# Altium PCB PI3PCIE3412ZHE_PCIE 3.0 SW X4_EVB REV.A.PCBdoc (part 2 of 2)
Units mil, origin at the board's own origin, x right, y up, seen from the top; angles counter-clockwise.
Board outline 3399 x 2712 mil, 8 copper layers (TopLayer, InternalPlane1, MidLayer1, MidLayer2, MidLayer3, MidLayer4, InternalPlane2, BottomLayer); 24 components, 100 nets, 589 pads, 111 vias.
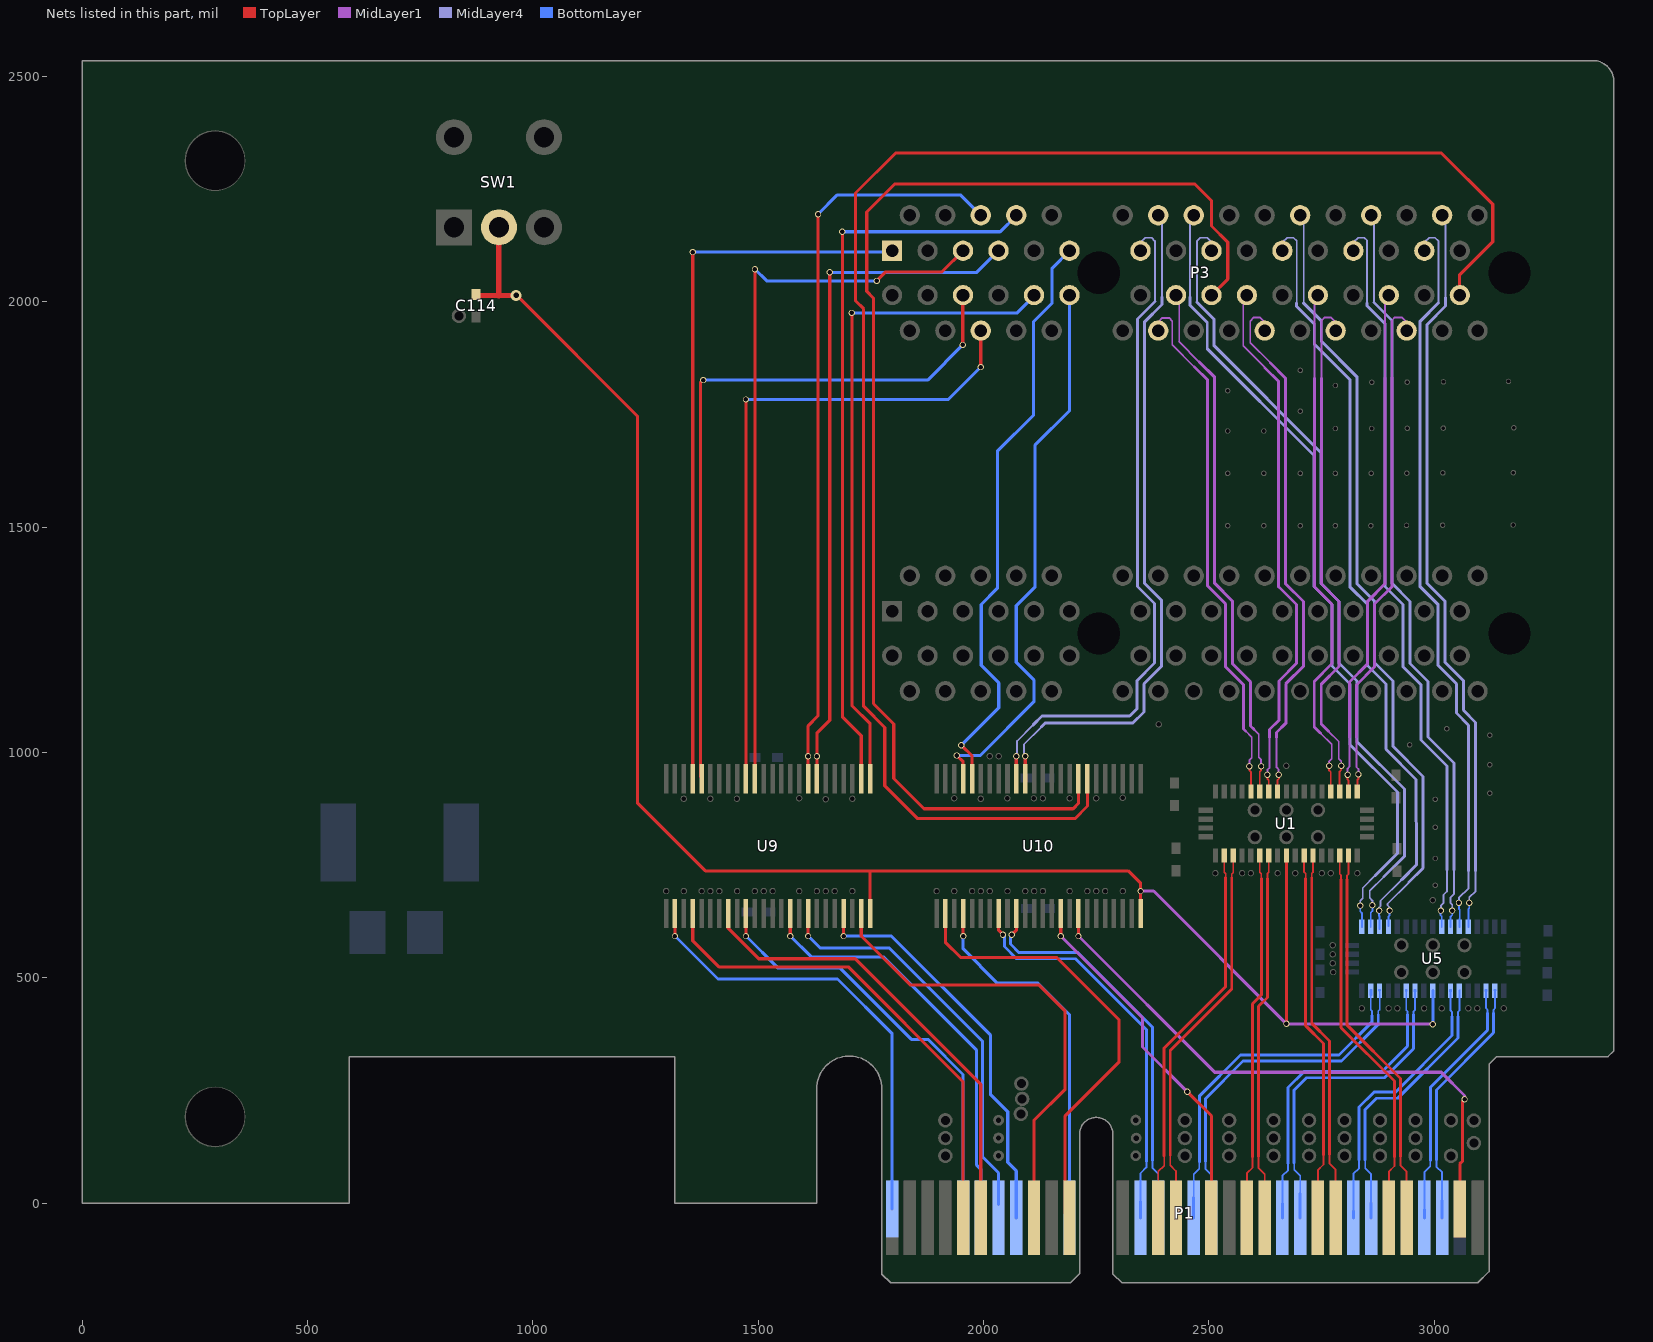
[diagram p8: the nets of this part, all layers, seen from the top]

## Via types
v1: diameter 14, hole 10, TopLayer to BottomLayer, tented both sides, 49 vias
v2: diameter 32, hole 20, TopLayer to BottomLayer, tented both sides, 40 vias
v3: diameter 24, hole 12, TopLayer to BottomLayer, tented both sides, 17 vias
v4: diameter 20, hole 10, TopLayer to BottomLayer, 5 vias

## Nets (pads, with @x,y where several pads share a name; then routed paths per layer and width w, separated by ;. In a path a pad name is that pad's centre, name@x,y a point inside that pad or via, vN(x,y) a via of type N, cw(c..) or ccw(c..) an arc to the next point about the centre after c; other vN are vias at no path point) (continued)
S1_JTAG1: P3.B9 U9.25 | length 1473.6
  TopLayer w7: v1(1708,1975) 1708,1934.76 1708,1104 1748.62,1063.38 U9.25@1748.62,941.61
  BottomLayer w7: v1(1708,1975) 2075.38,1975.38 P3.B9@2115,2015
S1_JTAG2: P3.A5 U9.38 | length 1632.3
  TopLayer w7: U9.38@1492.72,941.61 v1@1492.72,2072 ; v1(1763,2046) 1783,2066 1908,2066 P3.A5@1956,2114
  BottomLayer w7: v1(1493,2072) 1519,2046 v1(1763,2046)
S1_JTAG3: P3.A6 U9.32 | length 1660.2
  TopLayer w7: U9.32@1610.83,941.61 1610.83,1058.83 1633,1081 v1@1633,2195
  BottomLayer w7: v1(1633,2194) 1676,2237 1948.83,2237 P3.A6@1994.09,2191.73
  other v1: 1610.83,991.53
S1_JTAG4: P3.A7 U9.31 | length 1530.5
  TopLayer w7: U9.31@1630.51,941.61 1630.51,1042.51 1659,1071 v1(1659,2065)
  BottomLayer w7: v1(1659,2065) 1985,2065 P3.A7@2034,2114
  other v1: 1630.51,991.53
S1_JTAG5: P3.A8 U9.26 | length 1631.6
  TopLayer w7: v1(1687,2155) 1687,1079 1728.94,1037.06 U9.26@1728.94,943.06
  BottomLayer w7: v1@1686,2155 2037,2155 P3.A8@2073.28,2191.28
S1_PERN0: P3.A17 pad.2 U5.23 | length 1806.5
  MidLayer4 w4: 2473.5,1999 2473.5,2134.5 2481,2142 2497,2142 2505.91,2133.09 P3.A17@2505.91,2112.99 ; pad.2@2863,661 2863,671 2857,677 2857,692.5 2889,724.5
  MidLayer4 w6.5: 2473.5,1999 2512,1960.5 2512,1902 2749,1665 2749,1375 2789,1335 2789,1198.5 2829,1158.5 2829,1023.5 2934,918.5 2934,769.5 2889,724.5
  BottomLayer w4: U5.23@2859.45,611.88 2859.45,644.45 2863,648 pad.2@2863,659
S1_PERN1: P3.A22 pad.4 U5.25 | length 1727
  MidLayer4 w4: P3.A22@2702,2191 2710.5,2186 2710.5,1996.5 ; pad.4@2901,649 2901,656 2896.5,660.5 2896.5,664 2944.5,712
  MidLayer4 w6.5: 2710.5,1996.5 2749.5,1957.5 2749.5,1912.5 2828.5,1833.5 2828.5,1374.5 2867.5,1335.5 2867.5,1199.5 2908.5,1158.5 2908.5,1013.5 2975.5,946.5 2975.5,743 2944.5,712
  BottomLayer w4: U5.25@2899,614 2899,636 2901,638 pad.4@2901,649
S1_PERN2: P3.A26 pad.6 U5.32 | length 1661.9
  MidLayer4 w4: P3.A26@2860,2191 2866.5,2185 2866.5,1998 ; pad.6@3040,649 3040,662 3036,666 3036,677 3044,685 3044,739
  MidLayer4 w6.5: 2866.5,1998 2906.5,1958 2906.5,1375 2946.5,1335 2946.5,1197 2986.5,1157 2986.5,1034 3044,976.5 3044,739
  BottomLayer w4: U5.32@3036.61,611.88 3036.61,635.61 3040,639 pad.6@3040,649
S1_PERN3: P3.A30 pad.8 U5.34 | length 1650.9
  MidLayer4 w4: P3.A30@3017.42,2191.34 3025.5,2183.26 3025.5,2009.5 ; pad.8@3078,666 3078,678 3092,692 3092,736.5
  MidLayer4 w6.5: 3025.5,2009.5 3025.5,1990.5 2984.5,1949.5 2984.5,1374.5 3024.5,1334.5 3024.5,1199.5 3065,1159 3065,1093.5 3092,1066.5 3092,736.5
  BottomLayer w4: U5.34@3075.98,611.88 3076,652 3078,654 pad.8@3078,666
S1_PERP0: P3.A16 pad.1 U5.22 | length 1809.3
  MidLayer4 w4: 2458,2010 2458,2183.1 P3.A16@2466.24,2191.34 ; pad.1@2836,660 2836,671 2841.5,676.5 2841.5,699 2869.5,727
  MidLayer4 w6.5: 2458,2010 2458,1992 2496.5,1953.5 2496.5,1895.5 2733.5,1658.5 2733.5,1368 2773.5,1328 2773.5,1191.5 2813.5,1151.5 2813.5,1017 2918.5,912 2918.5,776 2869.5,727
  BottomLayer w4: pad.1@2836,660 2836,647 2839.76,643.24 U5.22@2839.76,611.88
S1_PERP1: P3.A21 pad.3 U5.24 | length 1728.7
  MidLayer4 w4: P3.A21@2663.39,2112.99 2663.39,2131.39 2674,2142 2688,2142 2695,2135 2695,1997 ; pad.3@2878,649 2878,656 2881,659 2881,670.5 2928,717.5
  MidLayer4 w6.5: 2695,1997 2695,1989.5 2734,1950.5 2734,1906 2813,1827 2813,1367.5 2852,1328.5 2852,1192.5 2893,1151.5 2893,1007 2960,940 2960.5,750 2928,717.5
  BottomLayer w4: pad.3@2878,649 2878,637 2879,636 U5.24@2879,608
S1_PERP2: P3.A25 pad.5 U5.31 | length 1660.3
  MidLayer4 w4: P3.A25@2820.87,2112.99 2820.87,2131.39 2831.48,2142 2845.48,2142 ; 2845,2142 2851,2136 2851,1997 ; pad.5@3015,649 3015,660 3020.5,665.5 3020.5,683.5 3028.5,691.5 3028.5,739
  MidLayer4 w6.5: 2851,1997 2851,1991 2891,1951 2891,1368 2931,1328 2931,1190 2971,1150 2971,1027.5 3028.5,970 3028.5,739
  BottomLayer w4: pad.5@3014,649 3014,639 3016.93,636.07 U5.31@3016.93,611.88
S1_PERP3: P3.A29 pad.7 U5.33 | length 1652.1
  MidLayer4 w4: 2978.35,2131.39 2988.96,2142 ; 2988,2142 3002,2142 3010,2134 3010,1997.5 ; pad.7@3055,666 3055,677 3076.5,698.5 3076.5,736.5
  MidLayer4 w6.5: P3.A29@2978.35,2112.99 2978.35,2131.39 ; 3010,1997.5 2969,1956.5 2969,1367.5 3009,1327.5 3009,1192.5 3049.5,1152 3049.5,1087 3076.5,1060 3076.5,736.5
  BottomLayer w4: pad.7@3055,666 3054.88,653.1 3056.86,651.08 U5.33@3056.5,611.88
S1_PERST#: P3.A11 U10.44 | length 1312.9
  TopLayer w7: v1(1951,1016) 1974.61,992.39 U10.44@1974.61,941.61
  BottomLayer w7: v1(1951,1016) 2034,1099 2034,1154.24 1995,1193.24 1995,1328 2031,1364 2031,1668 2111,1748 2111,1955.76 2152.24,1997 2152.24,2074.3 P3.A11@2190.95,2112.99
S1_PETN0: P3.B15 pad.14 U1.33 | length 1182.6
  TopLayer w4: U1.33@2613.19,911.88 2613.04,957.03 2616.03,960.03 pad.14@2616,969
  MidLayer1 w4: P3.B15@2427.17,2014.57 P3.B15@2434.74,2007 ; 2434,1911 2479,1866 ; 2434.5,1911 P3.B15@2434.5,2007 ; 2600,1051 2611,1040 2611,989 2616,984 pad.14@2616,969
  MidLayer1 w6.5: 2479,1866 2513,1832.5 2513,1375 2552.5,1335.5 2552.5,1196.5 2592.5,1156.5 2592.5,1058.5 2600,1051
S1_PETN1: P3.B20 pad.16 U1.31 | length 1183.7
  TopLayer w4: U1.31@2652.56,908.14 2652.56,938.56 2656,942 pad.16@2656,950
  MidLayer1 w4: P3.B20@2624.02,1935.83 2624.02,1953.98 2613,1965 2600,1965 2592,1957 2592,1908.5 2637,1864 ; 2650.5,1033 2650.5,966.5 2655,962 pad.16@2655,950
  MidLayer1 w6.5: 2637,1864 2670.5,1830 2670.5,1374 2710,1334.5 2710,1191 2671,1152 2671,1064.5 2650.5,1044 2650.5,1033
S1_PETN2: P3.B24 pad.18 U1.24 | length 1153.6
  TopLayer w4: U1.24@2790.35,911.88 2790.35,957.35 2794,961 pad.18@2794,970
  MidLayer1 w4: 2750,1831 2750,1958 2757,1965 2770.48,1965 2781.5,1953.98 P3.B24@2781.5,1935.83 ; 2765.5,1047 2788.5,1024 ; 2788.41,1021.83 2788.41,985.59 2794,980 pad.18@2794,970
  MidLayer1 w6.5: 2750,1831 2750,1373.5 2789,1334.5 2789,1190.5 2749.5,1151 2749.5,1063 2765.5,1047
S1_PETN3: P3.B28 pad.20 U1.22 | length 1143.8
  TopLayer w4: U1.22@2829.72,908.14 2829.72,938.72 2832,941 pad.20@2832,951
  MidLayer1 w4: 2827.5,1033.5 2827.5,967.5 2832,963 pad.20@2832,951 ; 2906.5,1831.5 2906.5,1958.54 2912.96,1965 2927.96,1965 2938.98,1953.98 P3.B28@2938.98,1935.83
  MidLayer1 w6.5: 2827.5,1033.5 2827.5,1149.5 2868,1190 2868,1329 2906.5,1367.5 2906.5,1831.5
S1_PETP0: P3.B14 pad.13 U1.34 | length 1178.7
  TopLayer w4: pad.13@2590,969 2590,960 2593.5,956.5 U1.34@2593.5,911.88
  MidLayer1 w4: P3.B14@2387.8,1935.83 2387.8,1954.8 2397,1964 2412,1964 2419,1957 2419,1904.5 2468,1855 ; 2581.5,1047.5 2595.5,1033.5 2595.5,988 2590,982.5 pad.13@2590,969
  MidLayer1 w6.5: 2468,1855 2497.5,1826 2497.5,1369 2537,1329.5 2537,1190 ; 2537.24,1190 2577,1150 2577,1052 2581.5,1047.5
S1_PETP1: P3.B19 pad.15 U1.32 | length 1185.9
  TopLayer w4: pad.15@2630,950 2630,941 2632.87,938.13 U1.32@2632.87,908.14
  MidLayer1 w4: P3.B19@2584.35,2014.17 2576.5,2006.33 2576.5,1902 2625,1853 ; pad.15@2630,950 2630,961 2635,966 2635,1032.5
  MidLayer1 w6.5: 2625,1853 2655,1823.5 2655,1367 ; 2635,1032.5 2635,1050.5 2655.5,1071 2655.5,1158.5 2694.5,1197.5 2694.5,1328 2655.5,1367
S1_PETP2: P3.B23 pad.17 U1.25 | length 1157.3
  TopLayer w4: pad.17@2767,970 2767,960 2770.67,956.33 U1.25@2770.67,911.88
  MidLayer1 w4: 2734.5,1830 2734.5,2006.35 P3.B23@2741.83,2013.67 ; 2747.5,1043 2773,1017.5 ; pad.17@2767,970 2767,980 2772.91,985.91 2772.91,1017.33
  MidLayer1 w6.5: 2734.5,1830 2734.5,1367.5 2773.5,1328.5 2773.5,1197 2734,1157.5 2734,1056.5 2747.5,1043
S1_PETP3: P3.B27 pad.19 U1.23 | length 1144.7
  TopLayer w4: pad.19@2808,950 2808,940 2810.04,937.96 U1.23@2810.04,908.14
  MidLayer1 w4: pad.19@2808,950 2808,964 2812,968 2812,1033.5 ; 2891,1831 2891,2005.87 P3.B27@2899.31,2014.17
  MidLayer1 w6.5: 2812,1033.5 2812,1156 2852.5,1196.5 2852.5,1335.5 2891,1374 2891,1831
S1_PRSNT1#: P3.A1 U9.45 | length 1606.4
  TopLayer w7: U9.45@1354.92,941.61 v1@1354.92,2110
  BottomLayer w7: v1(1355,2110) P3.A1@1793,2110
S1_PRSNT2#: P3.B17 U10.32 | length 2826.3
  TopLayer w7: U10.32@2210.83,941.61 2210.94,887.06 2198.88,875 1868,875 1801,942 1801,1063 1756,1108 1756,2008 1741,2023 1741,2199 1803,2261 2469,2261 2506,2224 2506,2168 2542,2132 2542,2050 P3.B17@2505,2013
S1_PRSNT3#: P3.B31 U10.31 | length 3627.1
  TopLayer w7: U10.31@2230.51,941.61 2230.89,903.12 2230.89,880.89 2203,853 1854,853 1781,926 1781,1055 1734,1102 1734,1984 1716,2002 1716,2241 1805,2330 3016,2330 3130,2216 3130,2133 3056,2059 P3.B31@3056,2012
S1_REFCLK+: P3.A13 pad.11 U10.39 | length 1524.1
  TopLayer w7.5: U10.39@2073.03,941.61 pad.11@2073.03,991.53
  MidLayer4 w4: pad.11@2073,991 2074.5,993 2074.5,1025 2110.5,1061 ; P3.A13@2348.43,2112.99 2348.42,2131.39 2359.04,2142 2373.04,2142 ; 2373,2142 2380.5,2134.5 2380.5,2000.5
  MidLayer4 w6.5: 2110.5,1061 2130,1080.5 2324.5,1080.5 2340.5,1096.5 2340.5,1159 2379.5,1198 2379.5,1330 2341.5,1368 2341.5,1961.5 2380.5,2000.5
S1_REFCLK-: P3.A14 pad.12 U10.38 | length 1526.8
  TopLayer w7.5: U10.38@2092.72,941.61 pad.12@2092.72,991.53
  MidLayer4 w4: pad.12@2092,991 2090,993 2090,1018 2129,1057 ; P3.A14@2387.49,2191.34 2396,2182.83 2396,2010
  MidLayer4 w6.5: 2129,1057 2137,1065 2331.5,1065 2356,1089.5 2356,1152 2395,1191 2395,1337.5 2357,1375.5 2357,1954.5 2396,1993.5 2396,2010
S1_SMCLK: P3.B5 U9.44 | length 1604.2
  TopLayer w7: U9.44@1372,946 1372,1820 v1(1378,1826) ; U9.44@1374.61,941.61 U9.44@1374.61,946 ; v1(1954,1904) P3.B5@1954,2013
  BottomLayer w7: v1(1378,1826) 1876,1826 v1(1954,1904)
S1_SMDAT: P3.B6 U9.39 | length 1473.2
  TopLayer w7: U9.39@1473.03,941.61 v1(1473,1783) ; v1(1994,1855) P3.B6@1994,1936
  BottomLayer w7: v1(1473,1783) 1922,1783 v1(1994,1855)
S1_WAKE#: P3.B11 U10.45 | length 1246.3
  TopLayer w7: v1(1941,993) 1954.92,979.08 U10.45@1954.92,941.61
  BottomLayer w7: v1(1941,993) 1993,993 2112,1112 2112,1160.83 2072.83,1200 2072.83,1326.16 ; 2072.83,1325 2114,1366.16 2114,1681 2190.94,1757.94 P3.B11@2190.95,2014.57
S_JTAG1: P1.B9 U9.23 | length 1058.5
  TopLayer w7: U9.23@1728.94,642.39 1728.94,592.47 1837.41,484 2123,484 2181.1,425.9 2181.1,252.43 2112.2,183.54 P1.B9@2112.2,-33
S_JTAG2: P1.A5 U9.10 | length 977.1
  TopLayer w7: v1(1473.03,592.47) U9.10@1473.03,642.39
  BottomLayer w7: v1(1473.03,592.47) 1543.5,522 1681,522 1840,363 1877,363 1954.72,285.28 P1.A5@1954.72,-33
S_JTAG3: P1.A6 U9.15 | length 885.2
  TopLayer w7: v1(1571.46,592.47) U9.15@1571.46,642.39
  BottomLayer w7: v1(1571.46,592.47) 1617.76,546.17 1777.83,546.17 1984.26,339.74 1984.26,85.12 1994.09,75.28 P1.A6@1994.09,26.06
S_JTAG4: P1.A7 U9.17 | length 911
  TopLayer w7: v1(1610.83,592.47) U9.17@1610.83,642.39
  BottomLayer w7: v1(1610.83,592.47) 1637.45,565.85 1791.15,565.85 1998,359 1998,102.24 2033.46,66.78 P1.A7@2033.46,-3.47
S_JTAG5: P1.A8 U9.21 | length 896.2
  TopLayer w7: v1(1689.57,592.47) U9.21@1689.57,642.39
  BottomLayer w7: v1(1689.57,592.47) 1795.53,592.47 2016,372 2016,240.39 2054,202.39 2054,90.24 2072.83,71.41 P1.A8@2072.83,-33
S_PERN0: P1.A17 U5.15 | length 799.8
  BottomLayer w4: 2492.5,92 2492.5,76.5 2505.91,63.09 P1.A17@2505.91,18 ; 2876,417 2876,426 2879.13,429.13 U5.15@2879.13,472.12
  BottomLayer w6.5: 2492.5,92 2492.5,231.5 2576,315 2794.5,315 2876,396.5 2876,417 ; P1.A17@2505.91,-33 P1.A17@2505.91,18 ; U5.15@2879.13,471.13 U5.15@2879.13,472.12
S_PERN1: P1.A22 U5.11 | length 723.4
  BottomLayer w4: 2689.5,89 2689.5,73.5 2702.76,60.24 P1.A22@2702.76,21 ; 2954.5,418 2954.5,425.5 2957.89,428.89 U5.11@2957.89,469.7
  BottomLayer w6.5: 2689.5,89 2689.5,251 2716.5,278 2890,278 2954.5,342.5 2954.5,418 ; P1.A22@2702.76,-33 P1.A22@2702.76,21 ; U5.11@2957.89,469.7 2957.88,471.14 U5.11@2957.87,472.12
S_PERN2: P1.A26 U5.6 | length 625.3
  BottomLayer w4: 2847,96 2847,77 2860.24,63.76 P1.A26@2860.24,0 ; 3053,414 3053,424.5 3056.5,428 3056.5,471.92 U5.6@3056.3,472.12
  BottomLayer w6.5: 2847,96 2847,207.5 2872,232.5 2919.5,232.5 3053,366 3053,414 ; P1.A26@2860.24,-33 P1.A26@2860.24,0
S_PERN3: P1.A30 U5.2 | length 564.2
  BottomLayer w4: 3005,95 3005,80.72 3017.72,68 P1.A30@3017.72,5 ; 3132,422 3132,429 3135,432 3135,471.1 U5.2@3135.04,471.13
  BottomLayer w6.5: 3005,95 3005,251 3132,378 3132,422 ; P1.A30@3017.72,-33 P1.A30@3017.72,5 ; U5.2@3135.04,471.13 U5.2@3135.04,472.12
S_PERP0: P1.A16 U5.16 | length 798.3
  BottomLayer w4: P1.A16@2466.53,12 2466.53,64 2479,76.47 2479,91 ; U5.16@2859.45,462 2859.45,428.55 2862.39,425.61 2862.39,416.11
  BottomLayer w6.5: P1.A16@2466.53,-33 P1.A16@2466.53,12 ; 2479,91 2479,237 2570.5,328.5 2789,328.5 2862.5,402 2862.5,416.11 ; U5.16@2859.45,462 U5.16@2859.45,472.12
S_PERP1: P1.A21 U5.12 | length 723.1
  BottomLayer w4: P1.A21@2663.39,-1 2663.39,60.39 2676,73 2676,88 ; U5.12@2938.18,471.13 2938,470.95 2938,428 2941,425 2941,418
  BottomLayer w6.5: P1.A21@2663.39,-33 P1.A21@2663.39,-1 ; 2676,88 2676,256.5 2711,291.5 2884.5,291.5 2941,348 2941,418 ; U5.12@2938.18,471.13 U5.12@2938.19,472.12
S_PERP2: P1.A25 U5.7 | length 624.7
  BottomLayer w4: P1.A25@2820.89,-17.44 2820.89,65 2833.5,77.61 2833.5,95 ; U5.7@3036.6,469.7 3036.6,427.4 3039.5,424.5 3039.5,414
  BottomLayer w6.5: P1.A25@2820.87,-33 P1.A25@2820.89,-17.44 ; 2833.5,95 2833.5,213 2866.5,246 2914,246 3039.5,371.5 3039.5,414 ; U5.7@3036.6,469.7 3036.61,471.13 U5.7@3036.61,472.12
S_PERP3: P1.A29 U5.3 | length 564.5
  BottomLayer w4: P1.A29@2978.35,-14 2978.35,68 2991.5,81.15 2991.5,94 ; U5.3@3115.37,470.18 3115.37,432.13 3118.5,429 3118.5,421
  BottomLayer w6.5: P1.A29@2978.35,-33 P1.A29@2978.35,-14 ; 2991.5,94 2991.5,256.5 3118.5,383.5 3118.5,421 ; U5.3@3115.37,470.18 3115.36,471.14 U5.3@3115.35,472.12
S_PERST#: P1.A11 U10.4 | length 825.9
  TopLayer w7: v1(1954.92,592.47) U10.4@1954.92,642.39
  BottomLayer w7: v1(1954.92,592.47) 1954.92,564.08 2031,488 2121,488 2190.94,418.06 P1.A11@2190.94,-33
S_PETN0: P1.B15 U1.3 | length 872.7
  TopLayer w4: 2414.5,106 2414.5,83.5 2426.96,71.04 P1.B15@2426.96,21.32 ; 2551,721 2551,730 2554.13,733.13 U1.3@2554.13,772
  TopLayer w6.5: 2414.5,106 2414.5,338.5 2551,475 2551,721 ; P1.B15@2427.06,21.32 P1.B15@2427.16,-33 ; U1.3@2554.13,771.13 U1.3@2554.13,775.86
S_PETN1: P1.B20 U1.7 | length 825.5
  TopLayer w4: 2610.59,102.9 2610.59,77.47 2624.02,64.05 P1.B20@2624.02,17 ; 2630,720 2630,731 2632.89,733.89 U1.7@2632.89,773.08
  TopLayer w6.5: 2610.5,103 2610.5,436.5 2630,456 2630,720 ; P1.B20@2624.02,-33 P1.B20@2624.02,17 ; U1.7@2632.89,771.13 2632.89,773.08 U1.7@2632.87,775.86
S_PETN2: P1.B24 U1.12 | length 832.8
  TopLayer w4: 2728.5,721 2728.5,731.5 2731.33,734.33 U1.12@2731.33,771.97 ; 2768,108 2768,86.97 2781.42,73.55 2781.42,2.07 P1.B24@2781.5,2
  TopLayer w6.5: 2728.5,721 2728.5,399 2768,359.5 2768,108 ; U1.12@2731.3,775.86 2731.33,771.97 U1.12@2731.3,771.13 ; P1.B24@2781.5,-33 P1.B24@2781.5,2
S_PETN3: P1.B28 U1.16 | length 864.8
  TopLayer w4: 2807,718 2807,727 2810,730 U1.16@2810,770.96 ; 2925.5,103 2925.5,82.48 2938.92,69.06 2938.92,29.06 2938.98,29 P1.B28@2938.98,11
  TopLayer w6.5: 2807,718 2807,394.5 2925.5,276 2925.5,103 ; U1.16@2810.04,770.96 U1.16@2810.04,775.86 ; P1.B28@2938.98,-33 P1.B28@2938.98,11
S_PETP0: P1.B14 U1.2 | length 872.1
  TopLayer w4: P1.B14@2387.91,13.58 2388.04,13.72 2388.04,70.04 2401,83 2401,104 ; U1.2@2534.45,771.13 2534.45,733.55 2537.5,730.5 2537.5,722
  TopLayer w6.5: P1.B14@2387.8,-33 P1.B14@2387.91,13.58 ; 2401,104 2401,344 2537.5,480.5 2537.5,722 ; U1.2@2534.45,771.13 U1.2@2534.45,775.86
S_PETP1: P1.B19 U1.6 | length 823.5
  TopLayer w4: P1.B19@2584.65,17 2584.65,65.69 2597,78.05 2597,102 ; U1.6@2613,772.44 2613,734 2616.5,730.5 2616.5,720
  TopLayer w6.5: P1.B19@2584.65,-33 P1.B19@2584.65,17 ; 2597,102 2597,442 2616.5,461.5 2616.5,720 ; U1.6@2613.17,772.43 U1.6@2613.19,775.86
S_PETP2: P1.B23 U1.11 | length 831.8
  TopLayer w4: U1.11@2711.5,773.77 2711.5,734.5 2715,731 2715,720 ; P1.B23@2742.13,14 2742.13,73.16 2754.5,85.54 2754.5,107
  TopLayer w6.5: U1.11@2711.61,773.77 U1.11@2711.61,775.86 ; 2715,720 2715,393.5 2754.5,354 2754.5,107 ; P1.B23@2742.13,-33 P1.B23@2742.13,14
S_PETP3: P1.B27 U1.15 | length 864.4
  TopLayer w4: U1.15@2790.38,770.22 2790.38,730.12 2793.5,727 2793.5,718 ; P1.B27@2899.61,-16 2899.61,69.68 2912,82.08 2912,102
  TopLayer w6.5: U1.15@2790.35,775.86 U1.15@2790.35,771.13 U1.15@2790.38,770.22 ; 2793.5,718 2793.5,389 2912,270.5 2912,102 ; P1.B27@2899.61,-33 P1.B27@2899.61,-16
S_PRSNT1#: P1.A1 U9.2 | length 1010.5
  TopLayer w7: v1(1315.55,592.47) U9.2@1315.55,642.39
  BottomLayer w7: v1(1315.55,592.47) 1411.07,496.95 1676.05,496.95 1797.24,375.76 P1.A1@1797.24,-13.32
S_PRSNT2#: P1.B17 U10.15 | length 813.9
  TopLayer w7: v1(2171.46,592.47) U10.15@2171.46,642.39 ; v1(2452.24,247) 2505.91,193.34 P1.B17@2505.91,-33
  MidLayer1 w7: v1(2171.46,592.47) 2353,410.93 2353,346.24 v1(2452.24,247)
S_PRSNT3#: P1.B31 U10.17 | length 1309.4
  TopLayer w7: v1(2210.83,592.47) U10.17@2210.83,642.39 ; P1.B31@3057.09,-13.32 3057.09,86.84 3063,92.61 3063,225.5 v1(3067.5,230)
  MidLayer1 w7: v1(2210.83,592.47) 2513.3,290 3016,290 3067.5,238.5 v1(3067.5,230)
S_REFCLK+: P1.A13 U10.8 | length 893
  TopLayer w7: U10.8@2033.66,642.39 2033.66,604.99 v1(2043.31,595.35)
  BottomLayer w4: P1.A13@2348.42,3 2348.42,66 2361.5,79.07 2361.5,92
  BottomLayer w6.5: v1(2043.31,595.35) 2046.5,592 2046.5,569 2073.5,542 2204,542 2361.5,384.5 2361.5,92 ; P1.A13@2348.42,-33 P1.A13@2348.42,3
S_REFCLK-: P1.A14 U10.10 | length 892.9
  TopLayer w7: v1(2062.99,595.35) 2073.03,605.39 U10.10@2073.03,642.39
  BottomLayer w4: 2375,94 2375,78 2387.8,65.2 P1.A14@2387.8,20
  BottomLayer w6.5: v1(2062.99,595.35) 2060,592 2060,574.5 2079,555.5 2209.5,555.5 2375,390 2375,94 ; P1.A14@2387.8,-33 P1.A14@2387.8,20
S_SMCLK: P1.B5 U9.4 | length 1092
  TopLayer w7: U9.4@1354.92,642.39 1354.92,582.08 1413,524 1700,524 1954.72,269.28 P1.B5@1954.72,-33
S_SMDAT: P1.B6 U9.8 | length 1033
  TopLayer w7: U9.8@1433.66,642.39 1433.66,609.34 1501,542 1715.24,542 1994.09,263.15 P1.B6@1994.09,-33
S_WAKE#: P1.B11 U10.2 | length 1013.6
  TopLayer w7: U10.2@1915.55,642.39 1915.55,578.45 1949,545 2162,545 2301,406 2301,313.28 2181.1,193.38 2181.1,-23.16 P1.B11@2190.94,-33
SEL_3.3: C114.1 SW1.2 U1.9 U5.9 U9.24 U10.24 | length 4050
  TopLayer w7: v3(963,2014) v3@964.24,2011 ; v3@964.24,2014 1232,1746.24 1232,888 1383,737 2321,737 2348.62,709.38 U10.24@2348.62,642.39 ; U9.24@1748.62,642.39 1748.62,737 ; v1(2672.24,397.76) U1.9@2672.24,771.13
  TopLayer w12: C114.1@874.24,2013.5 v3(963,2014) ; 924.24,2013.5 SW1.2@924.24,2165
  MidLayer1 w7: v1(2348.62,692.32) 2377.68,692.32 v1(2672.24,397.76) ; v1@2673,397 v1(2997.24,397)
  BottomLayer w7: v1(2997.24,397) U5.9@2997.24,471.13
pads on no net: P2.165 P2.166 P3.165 P3.166 SW1.4 SW1.5 U9.14 U10.14 U10.21 U10.23 U10.25 U10.26 U10.28 U10.29

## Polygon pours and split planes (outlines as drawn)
no net on TopLayer "bottom Layer-No Net" (hatched 45Degree grid 70 track 30, remove dead copper, pour order 1001): 1145,2510 1659,2510 1661,2512 1661,2360 1474,2173 1201,2173 1150,2173 1145,2168 1144,2169 1144,2511
no net on TopLayer "bottom Layer-No Net" (hatched 45Degree grid 70 track 30, remove dead copper, pour order 1000): 421,2512 736,2512 737,2511 737,1906 735,1904 956,1904 1118,1742 1118,909 1117,908 422,908 421,907 421,2512
+3.3V on TopLayer "bottom Layer-No Net" (solid, pour order 1000): 2049,324 2174,324 2174,278 2133,237 2080,184 2059,184 2059,254 2049,264 2049,324
+3.3V on MidLayer2 "bottom Layer-No Net" (solid, remove dead copper, pour order 1001): 25,2512 3358,2512 3377,2493 3377,348 2311,348 2124,161 2047,161 2047,245 1996,296 1943,349 25,349 25,2512
GND on MidLayer3 "bottom Layer-No Net" (solid, remove dead copper, pour order 1001): 25,349 25,2512 3358,2512 3377,2493 3377,348 3376,349 25,349
+12V on MidLayer3 "bottom Layer-No Net" (solid, remove dead copper, pour order 1000): 1246,2513 1948,2513 1948,2157 1916,2125 1919,2122 1919,1980 1958,1941 1958,1928.02 1958,1389 1916,1347 1916,1181 1946,1151 1946,832 1983,795 1983,85 1791,85 1791,343 1463,671 1246,888 1246,2513
no net on BottomLayer "bottom Layer-No Net" (hatched 45Degree grid 70 track 30, remove dead copper, pour order 1003): 1142,2512 1657,2512 1659,2514 1659,2300 1555,2196 1552,2199 1142,2199 1142,2512
+3.3V on BottomLayer "bottom Layer-No Net" (solid, pour order 1002): 2094.14,283 2159.14,283 2181.14,261 2181.14,159 2068.14,159 2068.14,283 2094.14,283
no net on BottomLayer "bottom Layer-No Net" (hatched 90Degree grid 70 track 30, remove dead copper, pour order 1000): 423,2513 424,2512 737,2512 737,1904 952,1904 1117,1739 1118,1738 1118,1027 421,1027 420,1026 423,1029 423,2513
GND on InternalPlane1 (split plane): 3358.92,2513.83 3365.37,2511.16 3370.91,2506.91 3375.16,2501.37 3377.83,2494.92 3378.74,2488 3378.66,2487.43 3378.69,2487.43 3378.61,2487 3378.61,346.45 3377.55,345.39 3139,345.39 3131.2,343.84 3124.58,339.42 3107.58,322.41 3103.15,315.8 3101.6,307.99 3101.6,90.2 2307.64,90.2 2307.64,153 2307.74,153 2305.78,167.88 2300.03,181.75 2290.9,193.65 2278.99,202.79 2265.12,208.53 2250.24,210.49 2235.36,208.53 2221.5,202.79 2209.59,193.65 2200.45,181.75 2194.71,167.88 2192.75,153 2192.85,153 2192.85,80.2 1794.64,80.2 1794.64,254 1794.69,254 1792.91,272.04 1787.65,289.38 1779.11,305.36 1767.61,319.37 1753.6,330.87 1737.62,339.41 1720.28,344.67 1702.24,346.45 1684.21,344.67 1666.87,339.41 1650.88,330.87 1636.88,319.37 1625.38,305.36 1616.84,289.38 1611.58,272.04 1609.8,254 1609.85,254 1609.85,20.39 1335.64,20.39 1335.64,325 1334.08,332.8 1329.66,339.42 1323.05,343.84 1315.24,345.39 611.96,345.39 604.24,350.55 594.49,352.49 584.73,350.55 576.46,345.02 570.94,336.75 569,327 569,27.49 27.73,27.49 27.73,2414.17 29.49,2423 27.55,2432.75 22.02,2441.02 20.39,2442.11 20.39,2514.61 3353,2514.61
GND on InternalPlane2 (split plane): 3358.92,2513.83 3365.37,2511.16 3370.91,2506.91 3375.16,2501.37 3377.83,2494.92 3378.74,2488 3378.66,2487.43 3378.69,2487.43 3378.61,2487 3378.61,346.45 3377.55,345.39 3139,345.39 3131.2,343.84 3124.58,339.42 3107.58,322.41 3103.15,315.8 3101.6,307.99 3101.6,90.2 2310,90.2 2307.64,89.73 2307.64,153 2307.74,153 2305.78,167.88 2300.03,181.75 2290.9,193.65 2278.99,202.79 2265.12,208.53 2250.24,210.49 2235.36,208.53 2221.5,202.79 2209.59,193.65 2200.45,181.75 2194.71,167.88 2192.75,153 2192.85,153 2192.85,80.2 1794.64,80.2 1794.64,254 1794.69,254 1792.91,272.04 1787.65,289.38 1779.11,305.36 1767.61,319.37 1753.6,330.87 1737.62,339.41 1720.28,344.67 1702.24,346.45 1684.21,344.67 1666.87,339.41 1650.88,330.87 1636.88,319.37 1625.38,305.36 1616.84,289.38 1611.58,272.04 1609.8,254 1609.85,254 1609.85,20.39 1335.64,20.39 1335.64,325 1334.08,332.8 1329.66,339.42 1323.05,343.84 1315.24,345.39 592.24,345.39 584.44,343.84 577.82,339.42 573.4,332.8 571.85,325 571.85,20.39 20.39,20.39 20.39,2514.61 3353,2514.61

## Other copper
TopLayer:
  rectangle net +12V: 1790,85 1865,250
  text "TOP LAYER" at 9673,-633 h80
  text "1" at 10323,-763 h80
BottomLayer:
  rectangle net +12V: 1815,75 1885,250
  text "BOTTOM LAYER" at 9673,-633 h80
  text "4" at 10323,-763 h80
InternalPlane1 (plane layer: these items are gaps in the copper):
  lines w20: 1780,70 2220,70 ; 2280,80 3117,80
  lines w30: 1773,-8 2212.24,-8 ; 1774.24,-123 2212.24,-123 ; 1774.24,-95 2213.24,-95 ; 1774.24,-66 2213.24,-66 ; 1774.24,-37 2213.24,-37 ; 1774.24,48 2213.24,48 ; 1775.24,-147 2213.24,-147 ; 1777.24,20 2213.24,20 ; 2287.24,-154 3112,-154 ; 2287.24,-111 3119.99,-111 ; 2287.24,-56 3120.99,-56 ; 2287.24,0 3121.99,0 ; 2287.24,58 3119.99,58 ; 2288.24,-83 3121.99,-83 ; 2288.24,-28 3121.99,-28 ; 2289.24,-140 3121.99,-140 ; 2289.24,29 3121.99,29
  lines w50: 4,2423 2.24,2421.24 2.24,2 594.49,2 594.49,327
  text "POWER PLANE LAYER" at 9673,-633 h80
  text "2" at 10323,-763 h80
InternalPlane2 (plane layer: these items are gaps in the copper):
  lines w20: 1780,70 2200,70 ; 2310,80 3120.8,80
  lines w30: 1774.24,-87 2213.24,-87 ; 1774.24,-62 2213.24,-62 ; 1774.24,-34 2213.24,-34 ; 1774.24,20 2213.24,20 ; 1775.24,49 2213.24,49 ; 1776,-142 2213.24,-142 ; 1776.24,-115 2213.24,-115 ; 1776.24,-6 2213.24,-6 ; 2287.24,-130 3120.99,-130 ; 2287.24,-76 3121.99,-76 ; 2287.24,-20 3121.99,-20 ; 2287.24,35 3121.99,35 ; 2288.24,-151 3121.99,-151 ; 2288.24,-103 3121.99,-103 ; 2288.24,7 3121.99,7 ; 2289.24,-48 3121.99,-48 ; 2289.24,61 3121.99,61
  text "GND PLANE LAYER" at 9673,-633 h80
  text "3" at 10323,-763 h80

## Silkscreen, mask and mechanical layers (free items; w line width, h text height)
TopOverlay:
  rectangle: 506,966 1167,1083
  text "A2" at 1717,2175 h60
  text "A1" at 1700,2097 h60
  text "B1" at 1704,1999 h60
  text "B2" at 1728,1917 h60
  text "A2" at 1722,1372 h35
  text "A1" at 1705,1294 h35
  text "PI3PCIE3412ZHE PCIE3.0 Switch" at 370,1201 h80
  text "B1" at 1709,1196 h35
  text "EVB REV.A" at 370,1122 h80
  text "B2" at 1733,1114 h35
  text "S/N:" at 363,1000 h80
  text "B1" at 1780,180 h60 r270
  text "B11" at 2160,180 h60 r270
  text "B12" at 2300,180 h60 r270
  text "TOP SILKSCREEN LAYER" at 9673,-633 h80
  text "5" at 10323,-763 h80
BottomOverlay:
  text "A1" at 1813,187 h60 r90
  text "A12" at 2328.74,183.53 h60 r90
  text "A11" at 2205,179 h60 r90
  text "1003DB062" at 426,65 h60
  text "BOTTOM SILKSCREEN LAYER" at 9673,-633 h80
  text "6" at 10323,-763 h80
TopPaste:
  text "TOP PASTE LAYER" at 9673,-633 h80
  text "TOP PASTE LAYER" at 9673,-633 h80
  text "TP" at 10303,-763 h80
BottomPaste:
  text "BOTTOM PASTE LAYER" at 9673,-633 h80
  text "BOTTOM PASTE LAYER" at 9673,-633 h80
  text "BP" at 10303,-763 h80
TopSolder:
  text "TOP SOLDER LAYER" at 9673,-633 h80
  text "7" at 10323,-763 h80
BottomSolder:
  text "BOTTOM SOLDER LAYER" at 9673,-633 h80
  text "8" at 10323,-763 h80
DrillGuide:
  text "DRILL GUIDE LAYER" at 9673,-633 h80
  text "10" at 10303,-763 h80
Mechanical1:
  lines w5: 0,0 592.24,0 592.24,325 1315.24,325 1315.24,0 1630.24,0 1630.24,254 cw(c1702.24,254) 1774.24,254 1774.24,-158 1794.24,-177 2193.24,-177 2213.24,-157 2213.24,153 cw(c2250.24,153) 2287.24,153 2287.24,-158 2307.24,-177 3097,-177 3122,-152 3121.99,307.99 3139,325 3385.99,325 3399,338 3399,2487 ccw(c3352,2488) 3353,2535 0,2535 0,0
  lines w10: 9643,-673 9643,-283 ; 10043,-803 10043,-673 ; 10043,-543 10043,-413 ; 10573,-543 10573,-413
  lines w12: 9123,-673 11503,-673 ; 9123,-543 11503,-543 ; 9123,-413 11503,-413 ; 9123,-283 11503,-283 ; 9123,-223 9573,-223 ; 9123,-173 9483,-173 ; 9123,-123 9573,-123 ; 10663,-223 11438,-223 ; 10663,-123 11448,-123 ; 10753,-173 11373,-173
  lines w15: 9123,-803 9123,-53 11503,-53 11503,-803 9123,-803
  text "Pericom" at 9803,-223 h180
  text "PCB NAME" at 9163,-373 h60
  text "PI3PCIE3412ZHE PCIE3.0 SW EVB" at 9673,-373 h80
  text "REV.A" at 11242,-374 h80
  text "DATE" at 9253,-503 h60
  text "1/26/2010" at 9663,-503 h80
  text "Drawn by" at 10073,-503 h60
  text "Haojie Ci" at 10683,-503 h80
  text "TITLE" at 9233,-633 h60
  text "SHEET NUMBER" at 9243,-763 h60
  text "OF       10" at 10543,-763 h80
Mechanical2:
  lines w5: 5884.54,-2450 -560.72,-2450 -560.72,3279 5885.24,3279 5885.24,-2450 ; -559.96,-2455.52 -559.96,-405.52 -559.96,-2455.52 ; -559.96,-2155.52 5865.04,-2155.52 -559.96,-2155.52 ; -559.96,-1755.52 5865.04,-1755.52 -559.96,-1755.52 ; -559.96,-1555.52 2115.04,-1555.52 -559.96,-1555.52 ; -559.96,-1330.52 2115.04,-1330.52 -559.96,-1330.52 ; -534.96,-1955.52 2115.04,-1955.52 -534.96,-1955.52 ; 1540.04,-2455.52 1540.04,-1330.52 1540.04,-2455.52 ; 2115.04,-2455.52 2115.04,-405.52 2115.04,-2455.52 ; 2115.04,-930.52 5865.04,-930.52 2115.04,-930.52 ; 3615.04,-2155.52 3615.04,-1755.52 3615.04,-2155.52 ; 4365.04,-2155.52 4365.04,-1755.52 4365.04,-2155.52 ; 4490.04,-2455.52 4490.04,-2155.52 4490.04,-2455.52
  lines w6: -559.96,-404.52 5890.04,-404.52
  text "TOLERENCES UNLESS" at -323.46,-639.03 h100
  text "PERICOM" at 3580.24,-781 h200
  text "OTHERWISE SPECIFIED" at -323.46,-794.03 h100
  text "FRACTIONS DEC  ANGLES" at -323.46,-944.03 h100
  text "+    +    +" at -34.96,-1155.52 h100
  text "-    -    -" at -34.96,-1205.52 h100
  text "ASSY  DRAWING" at 2962.5,-1257.5 h200
  text "DATE" at 1665.5,-1481.5 h68
  text "APPROVALS" at -407,-1485.5 h68
  text "PCIexpress" at 3625,-1596 h125
  text "DRAWN" at -409.96,-1680.52 h68
  text "CHECKED" at -434.96,-1880.52 h68
  text "SIZE" at 3665.04,-1880.52 h68
  text "SCALE" at 2215.04,-1905.52 h68
  text "DRAWING NO." at 4440.04,-1905.52 h68
  text "B" at 4055.04,-2069.52 h113
  text "REF  PI2PCI412" at -395.96,-2103.52 h100
  text "SHEET" at 4540.04,-2305.52 h68
  text "DO NOT SCALE DRAWING" at 2240.04,-2330.52 h68
  text "DO NOT SCALE DRAWING" at 2240.04,-2330.52 h68
  text "REV" at -384.96,-2355.52 h113
  text "1 OF 2" at 5015.04,-2355.52 h113
  text "2.0" at 1705.04,-2364.52 h113
DrillDrawing:
  lines w4: -454.7,-177 1635.24,-177 ; 1715.24,345 1720.24,345 2895.24,1520 5700,1520 ; 2210.24,-175 2320.24,-285 2565.24,-285 ; 2255.24,200 3095.24,1040 5700,1040
  lines w5: 3398,-363 3399,-554 ; 17220.24,-1310 17220.24,9735 -1404.76,9740 -1404.76,-1305 17220.24,-1305
  lines w6: -474,2535 -99,2535 ; -455,190 2120,190 ; -454.76,0 -79.76,0 ; -454.7,325 357.24,325 ; 5.24,-620 5.24,-110 ; 592.24,-610 592.24,-100 ; 1315.24,-600 1315.24,-100 ; 1630.24,-600 1630.24,-100 ; 1774.24,-600 1774.24,-300 ; 2213.24,-570 2213.24,-300 ; 2287.24,-565 2287.24,-300
  lines w10: 6693.74,-95.14 7508.74,-95.14 ; 6703.74,429.86 7293.74,429.86 ; 6863.74,-315.14 6863.74,-95.14 6938.74,-170.14 6793.74,-170.14 6868.74,-95.14 ; 6863.74,429.86 6938.74,504.86 6793.74,504.86 6868.74,429.86 6868.74,649.86 ; 7258.74,-870.14 8333.74,-870.14 ; 7268.74,-850.14 8318.74,-850.14 ; 7428.74,-435.14 7648.74,-435.14 7573.74,-510.14 7573.74,-365.14 7648.74,-440.14 ; 7648.74,-610.14 7648.74,-210.14 ; 7683.74,1804.86 7683.74,2169.86 ; 7768.74,-605.14 7768.74,-195.14 ; 7768.74,-430.14 7843.74,-505.14 7843.74,-360.14 7768.74,-435.14 7988.74,-435.14 ; 7963.74,379.86 8573.74,2104.86 ; 8303.74,1974.86 8303.74,1959.86 8323.74,1959.86 ; 8303.74,1979.86 8323.74,1979.86 8323.74,1964.86 ; 8513.74,1894.86 8588.74,1819.86 8588.74,1964.86 8513.74,1889.86 8733.74,1889.86 ; 10214.5,8256 11459.5,8271 ; 10315,7665 11460,7675 ; 10329.5,7094.5 11469.5,7084.5 ; 10335,6740 11485,6790 ; 10360,6105 11510,6200 ; 10681.5,7368 11206.5,7363 ; 10768.5,6403.5 11443.5,6493.5 ; 10795,7970 11450,7970 ; 10975,7970 11445,7970 ; 11570,7970 12450,7970 12465,7970 ; 11570,8265 12470,8265 ; 11585,7675 12465,7675 12480,7675 ; 11585,7970 12485,7970 ; 11595,7085 12475,7085 12490,7085 ; 11595,7675 12495,7675 ; 11620,6495 12500,6495 12515,6495 ; 11620,7085 12520,7085 ; 11635,6200 12515,6200 12530,6200 ; 11635,6495 12535,6495 ; 11645,6200 12545,6200 ; 12490,7380 12475,7380 11595,7380 12495,7380 ; 12515,6790 12500,6790 11620,6790 12520,6790 ; 12595,8265 13075,8265 ; 12610,7970 13090,7970 ; 12615,7970 13085,7970 ; 12620,7380 13100,7380 ; 12620,7675 13100,7675 12630,7675 ; 12640,7085 13110,7085 ; 12640,7380 13110,7380 ; 12645,6790 13125,6790 ; 12645,7085 13125,7085 ; 12660,6495 13140,6495 ; 12665,6495 13135,6495 ; 12665,6790 13135,6790 ; 12670,6200 13150,6200 12680,6200 ; 7443.74,419.86 7653.74,-100.14 7763.74,-100.14 7928.74,369.86 7928.74,1789.86 7783.74,1499.86 7683.74,1719.86 7683.74,1399.86 7503.74,1514.86 7503.74,1524.86 7443.74,1449.86 7443.74,419.86
  text "Trace/Gap/Trace" at 13259.99,8811.1 h100
  text "Diff IMPEDANCE" at 14494.99,8801.1 h100
  text "LAYER STACK-UP:" at 9220,8730 h100
  text "Design" at 13619,8653 h100
  text "REQUIRED/CAL" at 14494.99,8626.1 h100
  text "(Finished)" at 13519,8503 h100
  text "85" at 15141,8230.5 h100
  text "6.5/7/6.5 or 6/6/6" at 13313,8225 h100
  text "Layer 1: Top" at 9146.5,8220 h100
  text "7.5 SE 43" at 15759.99,8201.1 h100
  text "0.0045" at 12670,8070 h100
  text "XXXX" at 11605,7990 h250
  text "Layer 2: Plane 1 Gnd" at 9146.5,7923.5 h100
  text "0.008" at 12685,7775 h100
  text "XXXX" at 11620,7695 h250
  text "85" at 15119.5,7662 h100
  text "7.5 SE 43" at 15755,7643 h100
  text "6.5/9/6.5 or 6/7/6" at 13313,7635.5 h100
  text "Layer 3: Mid 1" at 9146.5,7627 h100
  text "XXXX" at 11630,7400 h250
  text "Layer 4: Mid 2" at 9146.5,7330.5 h100
  text "0.008" at 12685.5,7185 h100
  text "XXXX" at 11630,7105 h250
  text "Layer 5: Mid 3" at 9146.5,7033.5 h100
  text "85" at 15167.5,6826 h100
  text "XXXX" at 11655,6810 h250
  text "7.5 SE 43" at 15749,6805.5 h100
  text "6.5/9/6.5 or 6/7/6" at 13463.5,6793.5 h100
  text "Layer 6: Mid 4" at 9146.5,6699 h100
  text "0.008" at 12751.5,6590 h100
  text "XXXX" at 11655,6515 h250
  text "Layer 7: Plane 1 Gnd" at 9146.5,6387 h100
  text "0.0045" at 12733.5,6309 h100
  text "XXXX" at 11670,6220 h250
  text "7.5 SE 43" at 15725,6207 h100
  text "85" at 15098,6204 h100
  text "6.5/7/6.5 or 6/6/6" at 13451.5,6195 h100
  text "Layer 8: Bottom" at 9146.5,6098 h100
  text "Notes:  Copper thickness .5oz all layers, external finished to 1.0 oz" at 9270,5170 h100
  text "Total requested thickness = 0.062\"" at 9850,4900 h100
  text "1. Material : EPOXY GLASS, NEMA GRADE FR-4 (SHALL MEET UL94V-0) COPPER CLAD 1OZ./SQ.FT." at 9053.92,4318.49 h100
  text "INNER AND OUTER LAYERS.  TOTAL THICKNESS .057/.067." at 9268.92,4068.49 h100
  text "2. CIRCUITRY AND PLATED THRU HOLES SHALL BE ELECTROPLATED COPPER .001 TO .002 THICK." at 9063.92,3818.49 h100
  text "PLATING IN HOLES .001 MIN. THICK." at 9288.92,3593.49 h100
  text "3. SOLDERMASK BOTH SODES WITH HYSOL SR-1000 (LIQUID PHOTO-IMAGEABLE[LPI] FOR SURFACE" at 9078.92,3343.49 h100
  text "MOUNT) OR EQUIVALENT. HOLES, EDGE CONNECTOR AND TERMINAL AREAS SHALL BE FREE OF SOLDERMASK." at 9283.92,3088.49 h100
  text "4. ALL UNDIMENSIONED HOLES SHALL BE LOCATED WITHIN .003 IN. TRUE POSITION DIAMETER." at 9088.92,2833.49 h100
  text "5. SILKSCREEN LEGEND OVER SOLDERMASK ON BOTH SIDES OF PCB USING WHITE EPOXY INK." at 9093.92,2593.49 h100
  text "2.535" at -989,2476 h100
  text "6. LAYER TO LAYER REGISTRATION TO BE WITHIN +/- .003." at 9108.92,2348.49 h100
  text "C" at 7633.74,2264.86 h100
  text "L" at 7678.74,2204.86 h100
  text "7. LAYERS SHALL BE BONDED WITH GLASS CLOTH THERMOSETTING ADHESIVE SYSTEM COMPATIBLE" at 9108.92,2113.49 h100
  text "WITH THE BASE MATERIAL." at 9308.92,1903.49 h100
  text "20" at 8128.74,1834.86 h100
  text "8. FINISHED CONDUCTOR WIDTH SHALL BE +/- 10% OF THE ORIGINAL FILM MASTER." at 9093.92,1683.49 h100
  text "9. 12 MICRO INCHES OF FULL BODY GOLD ON BOTH SIDES" at 9098.92,1468.49 h100
  text "0.072 \"R\"" at 5780.24,1460 h100
  text "10. IMPEDANCE CONTROL OF ALL TRACES ON TOP AND BOTTOM LAYER FOR 50 OHMS" at 9028.92,1233.49 h100
  text "0.037 \"R\"" at 5805.24,975 h100
  text "+.010" at 7018.74,774.86 h60
  text ".071" at 6723.74,704.86 h100
  text "-.015" at 7021.74,699.86 h60
  text "0.325" at -915,265 h100
  text "0.190" at -910,115 h100
  text "\"0\"" at -775.76,-48 h100
  text "-0.177" at -1005,-245 h100
  text "0.020 X 45 degree CHAMFER (4 X)" at 2620.24,-340 h100
  text "+.005" at 8338.74,-405.14 h60
  text ".010" at 8043.74,-475.14 h100
  text "-.010" at 8345.74,-484.14 h60
  text "DRILL DRAWING LAYER" at 9673,-633 h80
  text "9" at 10323,-763 h80
  text "FINGER DETAIL" at 7318.74,-815.14 h100
  text "\"0\"" at 58.24,-930 h100 r90
  text "0.592" at 665.24,-1050 h100 r90
  text "1.315" at 1375.24,-1050 h100 r90
  text "1.630" at 1680.24,-1055 h100 r90
  text "3.399" at 3435.24,-1055 h100 r90
  text "1.774" at 1825.24,-1060 h100 r90
  text "2.213" at 2230.24,-1060 h100 r90
  text "2.287" at 2365.24,-1065 h100 r90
